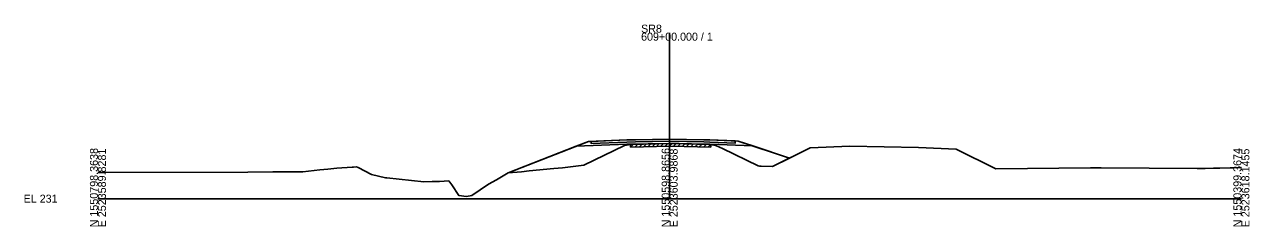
# Model space of a CAD drawing. Extents: x -26 to 2803, y -10 to 19537.
# Drawn here: x -25.7 to 402.8, y 14490.3 to 14560.8 of the extents above; entities that cross this region are included whole.
import ezdxf

# ---------------------------------------------------------------- set-up
doc = ezdxf.new("R2010")
doc.units = 0
for name, color, linetype in [('1', 7, 'Continuous'), ('Draft_XS_Grid', 7, 'Continuous'), ('Draft_XS_Text', 7, 'Continuous'), ('DTM_P_SUBGRADE_1', 7, 'Continuous'), ('DTM_X_GROUND', 7, 'Continuous'), ('SLOPE_STAKES_FILL', 7, 'Continuous'), ('XS_P_ASPHALT', 7, 'Continuous'), ('XS_P_SHOULDER', 7, 'Continuous')]:
    doc.layers.add(name, color=color, linetype=linetype)

msp = doc.modelspace()

# ---------------------------------------------------------------- linework, layer by layer
at = {"layer": '1'}
for p, q in [((200, 14500), (200, 14557.96)), ((0, 14500), (200, 14500)), ((200, 14500), (400, 14500))]:
    msp.add_line(p, q, dxfattribs=at)
at = {"layer": 'Draft_XS_Grid'}
for p, q in [((186.35, 14517.97), (187.38, 14518.99)), ((186.35, 14517.97), (186.35, 14518.97)), ((187.85, 14518), (188.88, 14519.03)), ((189.35, 14518.04), (190.38, 14519.07)), ((190.85, 14518.08), (191.88, 14519.1)), ((192.35, 14518.12), (193.38, 14519.14)), ((193.85, 14518.15), (194.88, 14519.18)), ((195.35, 14518.19), (196.38, 14519.22)), ((196.85, 14518.23), (197.88, 14519.25)), ((198.35, 14518.27), (199.38, 14519.29)), ((199.85, 14518.3), (200.86, 14519.31)), ((201.35, 14518.29), (202.33, 14519.27)), ((202.85, 14518.25), (203.83, 14519.23)), ((204.35, 14518.21), (205.33, 14519.19)), ((205.85, 14518.17), (206.83, 14519.15)), ((207.35, 14518.13), (208.33, 14519.11)), ((208.85, 14518.09), (209.83, 14519.06)), ((210.35, 14518.05), (211.33, 14519.02)), ((211.85, 14518.01), (212.83, 14518.98)), ((213.35, 14517.97), (214.33, 14518.94)), ((214.35, 14518.94), (214.35, 14517.94)), ((186.35, 14517.97), (200, 14518.31)), ((200, 14518.31), (200.45, 14518.32)), ((200.45, 14518.32), (214.35, 14517.94))]:
    msp.add_line(p, q, dxfattribs=at)
at = {"layer": 'Draft_XS_Text'}
for p, q in [((235.99, 14511.19), (249.17, 14517.77)), ((249.17, 14517.77), (263, 14518.32)), ((263, 14518.32), (275, 14518.08)), ((275, 14518.08), (287, 14517.84)), ((287, 14517.84), (300.21, 14517.31)), ((300.21, 14517.31), (314.14, 14510.37))]:
    msp.add_line(p, q, dxfattribs=at)
for points in [[(0, 14509.16), (2.43, 14509.17), (52.43, 14509.29), (61.16, 14509.36), (71.73, 14509.43), (77.65, 14510.07), (80.38, 14510.29), (83.53, 14510.6), (88.95, 14511.01), (89.41, 14511.05), (90.42, 14511.11), (91.01, 14510.89), (95.68, 14508.45), (100.63, 14507.33), (101.1, 14507.25), (114.02, 14505.89), (116.91, 14506.01), (119.44, 14506.04), (122.72, 14506.26), (123.8, 14504.78), (126.24, 14501.13), (128.88, 14500.71), (130.76, 14501.08), (136.62, 14505.04), (139.45, 14506.57), (143.52, 14509.02), (148.15, 14509.43), (150.83, 14509.71), (159.46, 14510.51), (162.51, 14510.76), (170.02, 14511.72), (184.15, 14518.56), (186.35, 14518.97), (200, 14519.31), (200.45, 14519.32), (214.35, 14518.94), (216.4, 14518.48), (218.43, 14517.49), (230.92, 14511.43), (231.42, 14511.4), (232.05, 14511.38), (235.99, 14511.19)], [(314.14, 14510.37), (347.21, 14510.74), (348.73, 14510.75), (349.13, 14510.75), (350.5, 14510.76), (350.96, 14510.76), (384.49, 14510.53), (387.32, 14510.54), (390.2, 14510.61), (392.41, 14510.62), (396.02, 14510.73), (397.33, 14510.74), (400, 14510.84)]]:
    msp.add_lwpolyline(points, dxfattribs=at)
at = {"layer": 'DTM_P_SUBGRADE_1'}
for p, q in [((185.07, 14519.01), (167.27, 14518.3)), ((200, 14519.31), (185.07, 14519.01)), ((200, 14519.31), (212, 14519.07)), ((212, 14519.07), (214, 14519.03)), ((214, 14519.03), (229.11, 14518.42))]:
    msp.add_line(p, q, dxfattribs=at)
at = {"layer": 'DTM_X_GROUND'}
for p, q in [((171.55, 14519.97), (143.52, 14509.02)), ((185.07, 14520.51), (171.55, 14519.97)), ((188, 14520.57), (185.07, 14520.51)), ((188, 14520.57), (200, 14520.81)), ((200, 14520.81), (212, 14520.57)), ((212, 14520.57), (214, 14520.53)), ((214, 14520.53), (224, 14520.13)), ((224, 14520.13), (241.92, 14514.15))]:
    msp.add_line(p, q, dxfattribs=at)
at = {"layer": 'SLOPE_STAKES_FILL'}
for p, q in [((143.52, 14509.02), (171.55, 14519.97)), ((171.55, 14519.97), (185.07, 14520.51)), ((185.07, 14520.51), (188, 14520.57)), ((188, 14520.57), (200, 14520.81)), ((200, 14520.81), (212, 14520.57)), ((212, 14520.57), (214, 14520.53)), ((214, 14520.53), (224, 14520.13)), ((224, 14520.13), (241.92, 14514.15)), ((241.92, 14514.15), (249.17, 14517.77)), ((249.17, 14517.77), (263, 14518.32)), ((263, 14518.32), (275, 14518.08)), ((275, 14518.08), (287, 14517.84)), ((287, 14517.84), (300.21, 14517.31)), ((300.21, 14517.31), (314.14, 14510.37))]:
    msp.add_line(p, q, dxfattribs=at)
for points in [[(0, 14509.16), (2.43, 14509.17), (52.43, 14509.29), (61.16, 14509.36), (71.73, 14509.43), (77.65, 14510.07), (80.38, 14510.29), (83.53, 14510.6), (88.95, 14511.01), (89.41, 14511.05), (90.42, 14511.11), (91.01, 14510.89), (95.68, 14508.45), (100.63, 14507.33), (101.1, 14507.25), (114.02, 14505.89), (116.91, 14506.01), (119.44, 14506.04), (122.72, 14506.26), (123.8, 14504.78), (126.24, 14501.13), (128.88, 14500.71), (130.76, 14501.08), (136.62, 14505.04), (139.45, 14506.57), (143.52, 14509.02)], [(314.14, 14510.37), (347.21, 14510.74), (348.73, 14510.75), (349.13, 14510.75), (350.5, 14510.76), (350.96, 14510.76), (384.49, 14510.53), (387.32, 14510.54), (390.2, 14510.61), (392.41, 14510.62), (396.02, 14510.73), (397.33, 14510.74), (400, 14510.84)]]:
    msp.add_lwpolyline(points, dxfattribs=at)
at = {"layer": 'XS_P_ASPHALT'}
for p, q in [((172.54, 14519.26), (172.54, 14520.01)), ((185.07, 14519.76), (172.54, 14519.26)), ((188, 14519.82), (185.07, 14519.76)), ((188, 14519.82), (200, 14520.06)), ((200, 14520.06), (212, 14519.82)), ((212, 14519.82), (214, 14519.78)), ((214, 14519.78), (222.97, 14519.42)), ((222.97, 14519.42), (222.97, 14520.17))]:
    msp.add_line(p, q, dxfattribs=at)
at = {"layer": 'XS_P_SHOULDER'}
for points in [[(184.15, 14518.56), (186.35, 14518.97), (200, 14519.31), (185.07, 14519.01), (167.27, 14518.3), (143.52, 14509.02), (148.15, 14509.43), (150.83, 14509.71), (159.46, 14510.51), (162.51, 14510.76), (170.02, 14511.72)], [(171.55, 14519.97), (167.27, 14518.3), (185.07, 14519.01), (200, 14519.31), (200.45, 14519.32), (203.3, 14519.24), (212, 14519.07), (214, 14519.03), (229.11, 14518.42), (224, 14520.13), (222.97, 14520.17), (222.97, 14519.42), (214, 14519.78), (212, 14519.82), (200, 14520.06), (188, 14519.82), (185.07, 14519.76), (172.54, 14519.26), (172.54, 14520.01)], [(188, 14519.82), (200, 14520.06), (212, 14519.82), (214, 14519.78), (222.97, 14519.42), (222.97, 14520.17), (214, 14520.53), (212, 14520.57), (200, 14520.81), (188, 14520.57), (185.07, 14520.51), (172.54, 14520.01), (172.54, 14519.26), (185.07, 14519.76)], [(200, 14519.31), (200.45, 14519.32), (203.3, 14519.24)], [(216.4, 14518.48), (218.43, 14517.49), (230.92, 14511.43), (231.42, 14511.4), (232.05, 14511.38), (235.99, 14511.19), (241.92, 14514.15), (229.11, 14518.42), (214, 14519.03), (212, 14519.07), (203.3, 14519.24), (214.35, 14518.94)]]:
    msp.add_lwpolyline(points, close=True, dxfattribs=at)

# ---------------------------------------------------------------- texts
at = {"layer": '1'}
for s, p in [('SR8', (190, 14557.96)), ('609+00.000 / 1', (190, 14555.16)), ('EL 231', (-26, 14498.6))]:
    msp.add_text(s, height=2.8, dxfattribs=at).set_placement(p)
for s, p in [('N 1550798.3638', (0, 14490)), ('E 2523589.8281', (2.8, 14490)), ('N 1550598.8656', (200, 14490)), ('E 2523603.9868', (202.8, 14490)), ('N 1550399.3674', (400, 14490)), ('E 2523618.1455', (402.8, 14490))]:
    msp.add_text(s, height=2.8, rotation=90, dxfattribs=at).set_placement(p)

doc.saveas('drawing.dxf')
